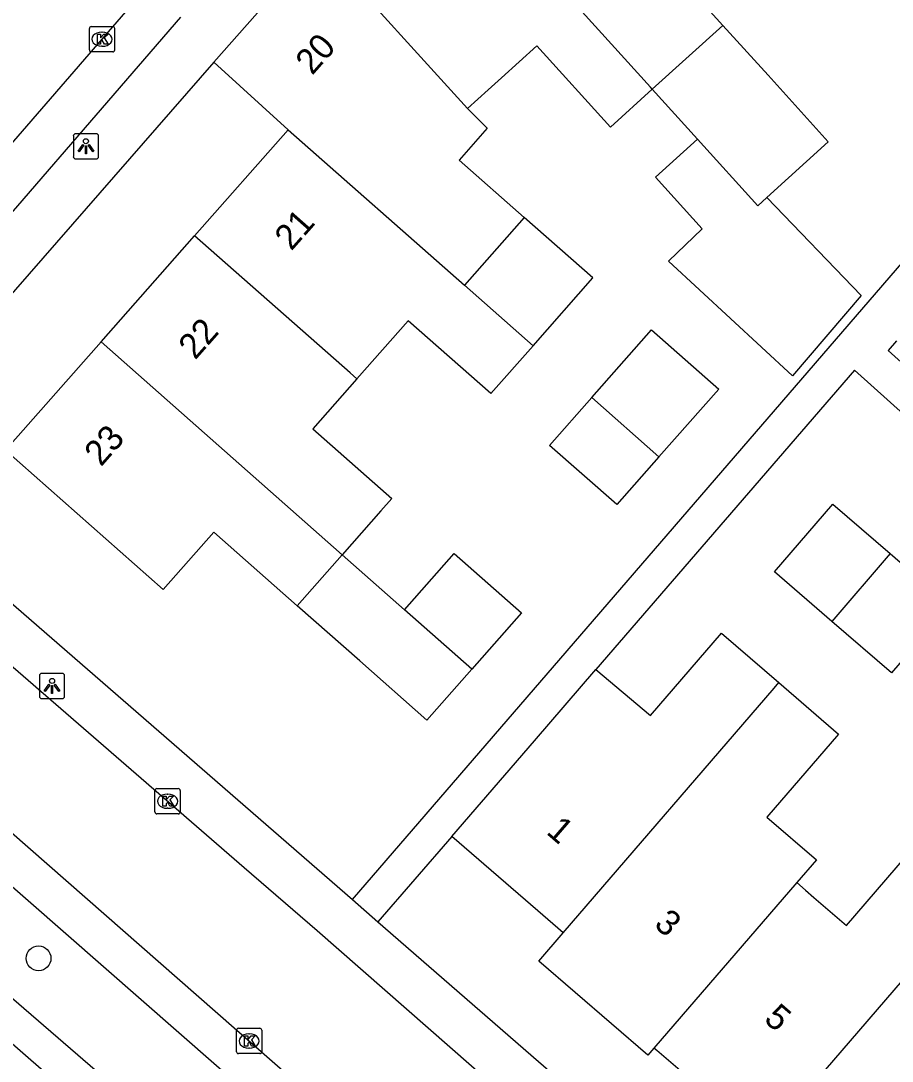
# Model space of a CAD drawing. Extents: x 158352 to 159489, y 383828 to 384597.
# Drawn here: x 159061.49 to 159095.97, y 384068.15 to 384109.3 of the extents above; entities that cross this region are included whole.
import ezdxf

# ---------------------------------------------------------------- set-up
doc = ezdxf.new("R2010")
doc.units = 0
for name, color, linetype in [('IMGEO_Boom', 7, 'Continuous'), ('IMGEO_Groenvoorziening', 7, 'Continuous'), ('IMGEO_Kolk', 7, 'Continuous'), ('IMGEO_Lichtpunt', 7, 'Continuous'), ('IMGEO_Pand', 7, 'Continuous'), ('IMGEO_Pand_nummerreeks', 7, 'Continuous'), ('IMGEO_Pand_overbouw', 7, 'Continuous'), ('IMGEO_Rijbaan_lokaal_open', 7, 'Continuous'), ('IMGEO_Voetpad_open', 7, 'Continuous')]:
    doc.layers.add(name, color=color, linetype=linetype)

msp = doc.modelspace()

# ---------------------------------------------------------------- linework, layer by layer
at = {"layer": 'IMGEO_Boom'}
msp.add_circle((159062.193, 384072.219), 0.489, dxfattribs=at)
at = {"layer": 'IMGEO_Groenvoorziening'}
msp.add_lwpolyline([(159047.486, 384082.448), (159082.23, 384052.422), (159084.241, 384054.827), (159049.737, 384085.023)], dxfattribs=at)
at = {"layer": 'IMGEO_Kolk'}
for p, q in [((159064.203, 384108.152), (159064.203, 384109.004)), ((159064.278, 384109.078), (159065.13, 384109.078)), ((159065.204, 384109.004), (159065.204, 384108.152)), ((159064.691, 384108.858), (159064.716, 384108.858)), ((159064.714, 384108.298), (159064.689, 384108.298)), ((159065.13, 384108.078), (159064.278, 384108.078)), ((159066.87, 384078.934), (159067.722, 384078.934)), ((159066.795, 384078.008), (159066.795, 384078.86)), ((159067.283, 384078.714), (159067.308, 384078.714)), ((159067.796, 384078.86), (159067.796, 384078.008)), ((159067.306, 384078.154), (159067.281, 384078.154)), ((159067.722, 384077.934), (159066.87, 384077.934)), ((159070.099, 384069.451), (159070.951, 384069.451)), ((159070.024, 384068.525), (159070.024, 384069.377)), ((159070.512, 384069.231), (159070.537, 384069.231)), ((159071.025, 384069.377), (159071.025, 384068.525)), ((159070.535, 384068.671), (159070.51, 384068.671)), ((159070.951, 384068.451), (159070.099, 384068.451))]:
    msp.add_line(p, q, dxfattribs=at)
for points in [[(159064.203, 384108.152), (159064.203, 384109.004)], [(159064.278, 384109.078), (159065.13, 384109.078)], [(159065.204, 384109.004), (159065.204, 384108.152)], [(159064.524, 384108.778), (159064.647, 384108.778), (159064.647, 384108.627), (159064.777, 384108.778), (159064.941, 384108.778), (159064.795, 384108.627), (159064.948, 384108.378), (159064.796, 384108.378), (159064.711, 384108.542), (159064.647, 384108.475), (159064.647, 384108.378), (159064.524, 384108.378), (159064.524, 384108.778)], [(159065.13, 384108.078), (159064.278, 384108.078)], [(159066.87, 384078.934), (159067.722, 384078.934)], [(159066.795, 384078.008), (159066.795, 384078.86)], [(159067.116, 384078.634), (159067.239, 384078.634), (159067.239, 384078.483), (159067.369, 384078.634), (159067.533, 384078.634), (159067.387, 384078.483), (159067.54, 384078.234), (159067.388, 384078.234), (159067.303, 384078.398), (159067.239, 384078.331), (159067.239, 384078.234), (159067.116, 384078.234), (159067.116, 384078.634)], [(159067.796, 384078.86), (159067.796, 384078.008)], [(159067.722, 384077.934), (159066.87, 384077.934)], [(159070.099, 384069.451), (159070.951, 384069.451)], [(159070.024, 384068.525), (159070.024, 384069.377)], [(159070.345, 384069.151), (159070.468, 384069.151), (159070.468, 384069), (159070.598, 384069.151), (159070.762, 384069.151), (159070.616, 384069), (159070.769, 384068.751), (159070.617, 384068.751), (159070.532, 384068.915), (159070.468, 384068.848), (159070.468, 384068.751), (159070.345, 384068.751), (159070.345, 384069.151)], [(159071.025, 384069.377), (159071.025, 384068.525)], [(159070.951, 384068.451), (159070.099, 384068.451)]]:
    msp.add_lwpolyline(points, dxfattribs=at)
for centre, start, end in [((159064.28, 384109.002), 91.552, 178.448), ((159064.28, 384109.002), 91.552, 178.448), ((159065.128, 384109.002), 1.552, 88.448), ((159065.128, 384109.002), 1.552, 88.448), ((159064.28, 384108.154), 181.552, 268.448), ((159064.28, 384108.154), 181.552, 268.448), ((159065.128, 384108.154), 271.552, 358.448), ((159065.128, 384108.154), 271.552, 358.448), ((159066.872, 384078.858), 91.552, 178.448), ((159066.872, 384078.858), 91.552, 178.448), ((159067.72, 384078.858), 1.552, 88.448), ((159067.72, 384078.858), 1.552, 88.448), ((159066.872, 384078.01), 181.552, 268.448), ((159066.872, 384078.01), 181.552, 268.448), ((159067.72, 384078.01), 271.552, 358.448), ((159067.72, 384078.01), 271.552, 358.448), ((159070.101, 384069.375), 91.552, 178.448), ((159070.101, 384069.375), 91.552, 178.448), ((159070.949, 384069.375), 1.552, 88.448), ((159070.949, 384069.375), 1.552, 88.448), ((159070.101, 384068.527), 181.552, 268.448), ((159070.101, 384068.527), 181.552, 268.448), ((159070.949, 384068.527), 271.552, 358.448), ((159070.949, 384068.527), 271.552, 358.448)]:
    msp.add_arc(centre, 0.0765, start, end, dxfattribs=at)
for centre, major_axis, ratio, start_param, end_param in [((159064.69, 384108.578), (-0.387, 0.002), 0.722429, 4.712389, 7.853982), ((159064.715, 384108.578), (-0.39, 0.002), 0.717154, 1.570796, 4.712389), ((159067.282, 384078.434), (-0.387, 0.002), 0.722429, 4.712389, 7.853982), ((159067.307, 384078.434), (-0.39, 0.002), 0.717154, 1.570796, 4.712389), ((159070.511, 384068.951), (-0.387, 0.002), 0.722429, 4.712389, 7.853982), ((159070.536, 384068.951), (-0.39, 0.002), 0.717154, 1.570796, 4.712389)]:
    msp.add_ellipse(centre, major_axis=major_axis, ratio=ratio, start_param=start_param, end_param=end_param, dxfattribs=at)
at = {"layer": 'IMGEO_Lichtpunt'}
for p, q in [((159064.471, 384104.84), (159063.663, 384104.84)), ((159064.471, 384104.84), (159063.663, 384104.84)), ((159063.569, 384104.745), (159063.569, 384103.938)), ((159063.569, 384104.745), (159063.569, 384103.938)), ((159064.565, 384103.938), (159064.565, 384104.745)), ((159064.565, 384103.938), (159064.565, 384104.745)), ((159063.663, 384103.844), (159064.471, 384103.844)), ((159063.663, 384103.844), (159064.471, 384103.844)), ((159063.13, 384083.49), (159062.322, 384083.49)), ((159063.13, 384083.49), (159062.322, 384083.49)), ((159062.228, 384083.395), (159062.228, 384082.588)), ((159062.228, 384083.395), (159062.228, 384082.588)), ((159063.224, 384082.588), (159063.224, 384083.395)), ((159063.224, 384082.588), (159063.224, 384083.395)), ((159062.322, 384082.494), (159063.13, 384082.494)), ((159062.322, 384082.494), (159063.13, 384082.494))]:
    msp.add_line(p, q, dxfattribs=at)
for points in [[(159063.943, 384104.409), (159063.982, 384104.381), (159063.794, 384104.119), (159063.756, 384104.146), (159063.943, 384104.409)], [(159064.045, 384104.361), (159064.092, 384104.361), (159064.092, 384104.039), (159064.045, 384104.039), (159064.045, 384104.361)], [(159064.155, 384104.381), (159064.193, 384104.408), (159064.38, 384104.146), (159064.341, 384104.118), (159064.155, 384104.381)], [(159062.602, 384083.059), (159062.641, 384083.031), (159062.453, 384082.769), (159062.415, 384082.796), (159062.602, 384083.059)], [(159062.814, 384083.031), (159062.852, 384083.058), (159063.039, 384082.796), (159063, 384082.768), (159062.814, 384083.031)], [(159062.704, 384083.011), (159062.751, 384083.011), (159062.751, 384082.689), (159062.704, 384082.689), (159062.704, 384083.011)]]:
    msp.add_lwpolyline(points, dxfattribs=at)
for centre in [(159064.068, 384104.543), (159062.727, 384083.193)]:
    msp.add_circle(centre, 0.0994, dxfattribs=at)
for centre, start, end in [((159063.663, 384104.745), 90, 180), ((159063.663, 384104.745), 90, 180), ((159064.471, 384104.745), 0, 90), ((159064.471, 384104.745), 0, 90), ((159063.663, 384103.938), 180, 270), ((159063.663, 384103.938), 180, 270), ((159064.471, 384103.938), 270, 0), ((159064.471, 384103.938), 270, 360), ((159062.322, 384083.395), 90, 180), ((159062.322, 384083.395), 90, 180), ((159063.13, 384083.395), 0, 90), ((159063.13, 384083.395), 0, 90), ((159062.322, 384082.588), 180, 270), ((159062.322, 384082.588), 180, 270), ((159063.13, 384082.588), 270, 0), ((159063.13, 384082.588), 270, 360)]:
    msp.add_arc(centre, 0.0946, start, end, dxfattribs=at)
at = {"layer": 'IMGEO_Pand'}
for points in [[(159086.474, 384106.597), (159086.403, 384106.676), (159077.905, 384116.061)], [(159087.97, 384113.786), (159086.364, 384112.332), (159089.267, 384109.125)], [(159069.128, 384107.669), (159073.079, 384112.15)], [(159073.507, 384112.078), (159079.161, 384105.832)], [(159089.267, 384109.125), (159086.474, 384106.597)], [(159089.267, 384109.125), (159091.055, 384107.15), (159093.437, 384104.518), (159091.009, 384102.32)], [(159086.474, 384106.597), (159084.815, 384105.095), (159081.902, 384108.313), (159080.505, 384107.048), (159079.983, 384106.576), (159079.161, 384105.832)], [(159072.068, 384104.995), (159069.128, 384107.669)], [(159088.263, 384104.622), (159086.474, 384106.597)], [(159079.161, 384105.832), (159079.942, 384105.054), (159078.833, 384103.797), (159081.408, 384101.526), (159079.042, 384098.843)], [(159068.367, 384100.799), (159072.068, 384104.995)], [(159072.068, 384104.995), (159079.042, 384098.843)], [(159091.009, 384102.32), (159094.732, 384098.436), (159092.019, 384095.26), (159087.114, 384099.798), (159088.45, 384101.079), (159086.603, 384103.12), (159088.263, 384104.622)], [(159091.009, 384102.32), (159090.645, 384101.991), (159088.263, 384104.622)], [(159064.666, 384096.602), (159068.367, 384100.799)], [(159074.786, 384095.136), (159074.515, 384095.375), (159068.367, 384100.799)], [(159079.042, 384098.843), (159081.757, 384096.448), (159080.09, 384094.557), (159076.818, 384097.441), (159074.786, 384095.136)], [(159084.076, 384094.402), (159086.443, 384097.087), (159089.106, 384094.739), (159086.738, 384092.054)], [(159072.427, 384086.169), (159069.126, 384089.079), (159067.128, 384086.813), (159060.887, 384092.316), (159064.666, 384096.602)], [(159064.666, 384096.602), (159074.206, 384088.186)], [(159074.786, 384095.136), (159073.043, 384093.16), (159076.164, 384090.407), (159075.734, 384089.92), (159074.206, 384088.186)], [(159086.738, 384092.054), (159085.073, 384090.165), (159082.41, 384092.512), (159084.076, 384094.402)], [(159084.076, 384094.402), (159086.738, 384092.054)], [(159093.573, 384085.548), (159091.303, 384087.507), (159093.617, 384090.189), (159095.887, 384088.23)], [(159074.206, 384088.186), (159072.427, 384086.169)], [(159074.206, 384088.186), (159076.676, 384086.007)], [(159076.676, 384086.007), (159078.634, 384088.228), (159081.296, 384085.88), (159079.338, 384083.659)], [(159095.887, 384088.23), (159093.573, 384085.548)], [(159095.887, 384088.23), (159098.245, 384086.195), (159095.932, 384083.513), (159093.573, 384085.548)], [(159079.338, 384083.659), (159077.561, 384081.643), (159074.898, 384083.991), (159072.427, 384086.169)], [(159079.338, 384083.659), (159076.676, 384086.007)], [(159084.24, 384083.642), (159086.404, 384081.83), (159089.213, 384085.085), (159091.484, 384083.126)], [(159078.545, 384077.034), (159081.812, 384080.82), (159084.24, 384083.642)], [(159082.952, 384073.233), (159091.292, 384082.903), (159091.484, 384083.126)], [(159091.484, 384083.126), (159093.843, 384081.091), (159091.008, 384077.804), (159092.965, 384076.115), (159092.187, 384075.214)], [(159082.952, 384073.233), (159082.738, 384073.417), (159081.949, 384074.098), (159078.545, 384077.034)], [(159092.187, 384075.214), (159092.54, 384074.91), (159092.868, 384074.627), (159094.155, 384073.517), (159096.937, 384076.742), (159099.284, 384074.718)], [(159092.187, 384075.214), (159086.542, 384068.669)], [(159090.857, 384064.947), (159099.175, 384074.591), (159099.284, 384074.718)], [(159086.542, 384068.669), (159086.301, 384068.39), (159081.985, 384072.112), (159082.952, 384073.233)], [(159090.857, 384064.947), (159087.486, 384067.855), (159086.649, 384068.577), (159086.542, 384068.669)]]:
    msp.add_lwpolyline(points, dxfattribs=at)
at = {"layer": 'IMGEO_Pand_overbouw'}
msp.add_lwpolyline([(159084.124, 384099.132), (159081.408, 384101.526), (159079.042, 384098.843), (159081.757, 384096.448)], close=True, dxfattribs=at)
at = {"layer": 'IMGEO_Rijbaan_lokaal_open'}
for points in [[(159054.813, 384097.177), (159068.118, 384112.515)], [(159089.071, 384059.415), (159073.221, 384073.303), (159070.333, 384075.803), (159055.21, 384088.896), (159054.182, 384089.791)], [(159050.8, 384086.238), (159080.25, 384060.43), (159085.805, 384055.65)], [(159081.812, 384050.789), (159081.639, 384050.956), (159076.165, 384055.717), (159046.647, 384081.489)]]:
    msp.add_lwpolyline(points, dxfattribs=at)
at = {"layer": 'IMGEO_Voetpad_open'}
for points in [[(159067.815, 384109.452), (159058.002, 384098.104)], [(159069.128, 384107.669), (159055.048, 384091.549)], [(159074.609, 384074.546), (159098.506, 384102.224), (159099.904, 384101.017), (159098.383, 384099.256)], [(159096.134, 384096.652), (159095.803, 384096.268), (159112.646, 384081.133), (159111.666, 384080.043), (159094.48, 384095.486), (159084.24, 384083.642)], [(159055.048, 384091.549), (159074.609, 384074.546)], [(159078.545, 384077.034), (159075.619, 384073.668)], [(159074.609, 384074.546), (159075.619, 384073.668)], [(159075.619, 384073.668), (159096.403, 384055.601), (159099.594, 384052.806)]]:
    msp.add_lwpolyline(points, dxfattribs=at)

# ---------------------------------------------------------------- texts
at = {"layer": 'IMGEO_Pand_nummerreeks'}
for s, rotation, p in [('20', 48.5983, (159073.02, 384107.123)), ('21', 48.5868, (159072.193, 384100.176)), ('22', 48.5877, (159068.39, 384095.863)), ('23', 48.5877, (159064.665, 384091.64)), ('1', 319.2169, (159082.242, 384077.173)), ('3', 319.2169, (159086.502, 384073.499)), ('5', 319.2169, (159090.848, 384069.75))]:
    msp.add_text(s, height=1, rotation=rotation, dxfattribs=at).set_placement(p)

doc.saveas('drawing.dxf')
